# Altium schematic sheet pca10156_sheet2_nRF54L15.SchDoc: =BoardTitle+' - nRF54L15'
size A3; Organization: Nordic Semiconductor; DocumentNumber: 2; SheetNumber: 2; SheetTotal: 7; CompanyName: Nordic Semiconductor; DocumentSize: A4
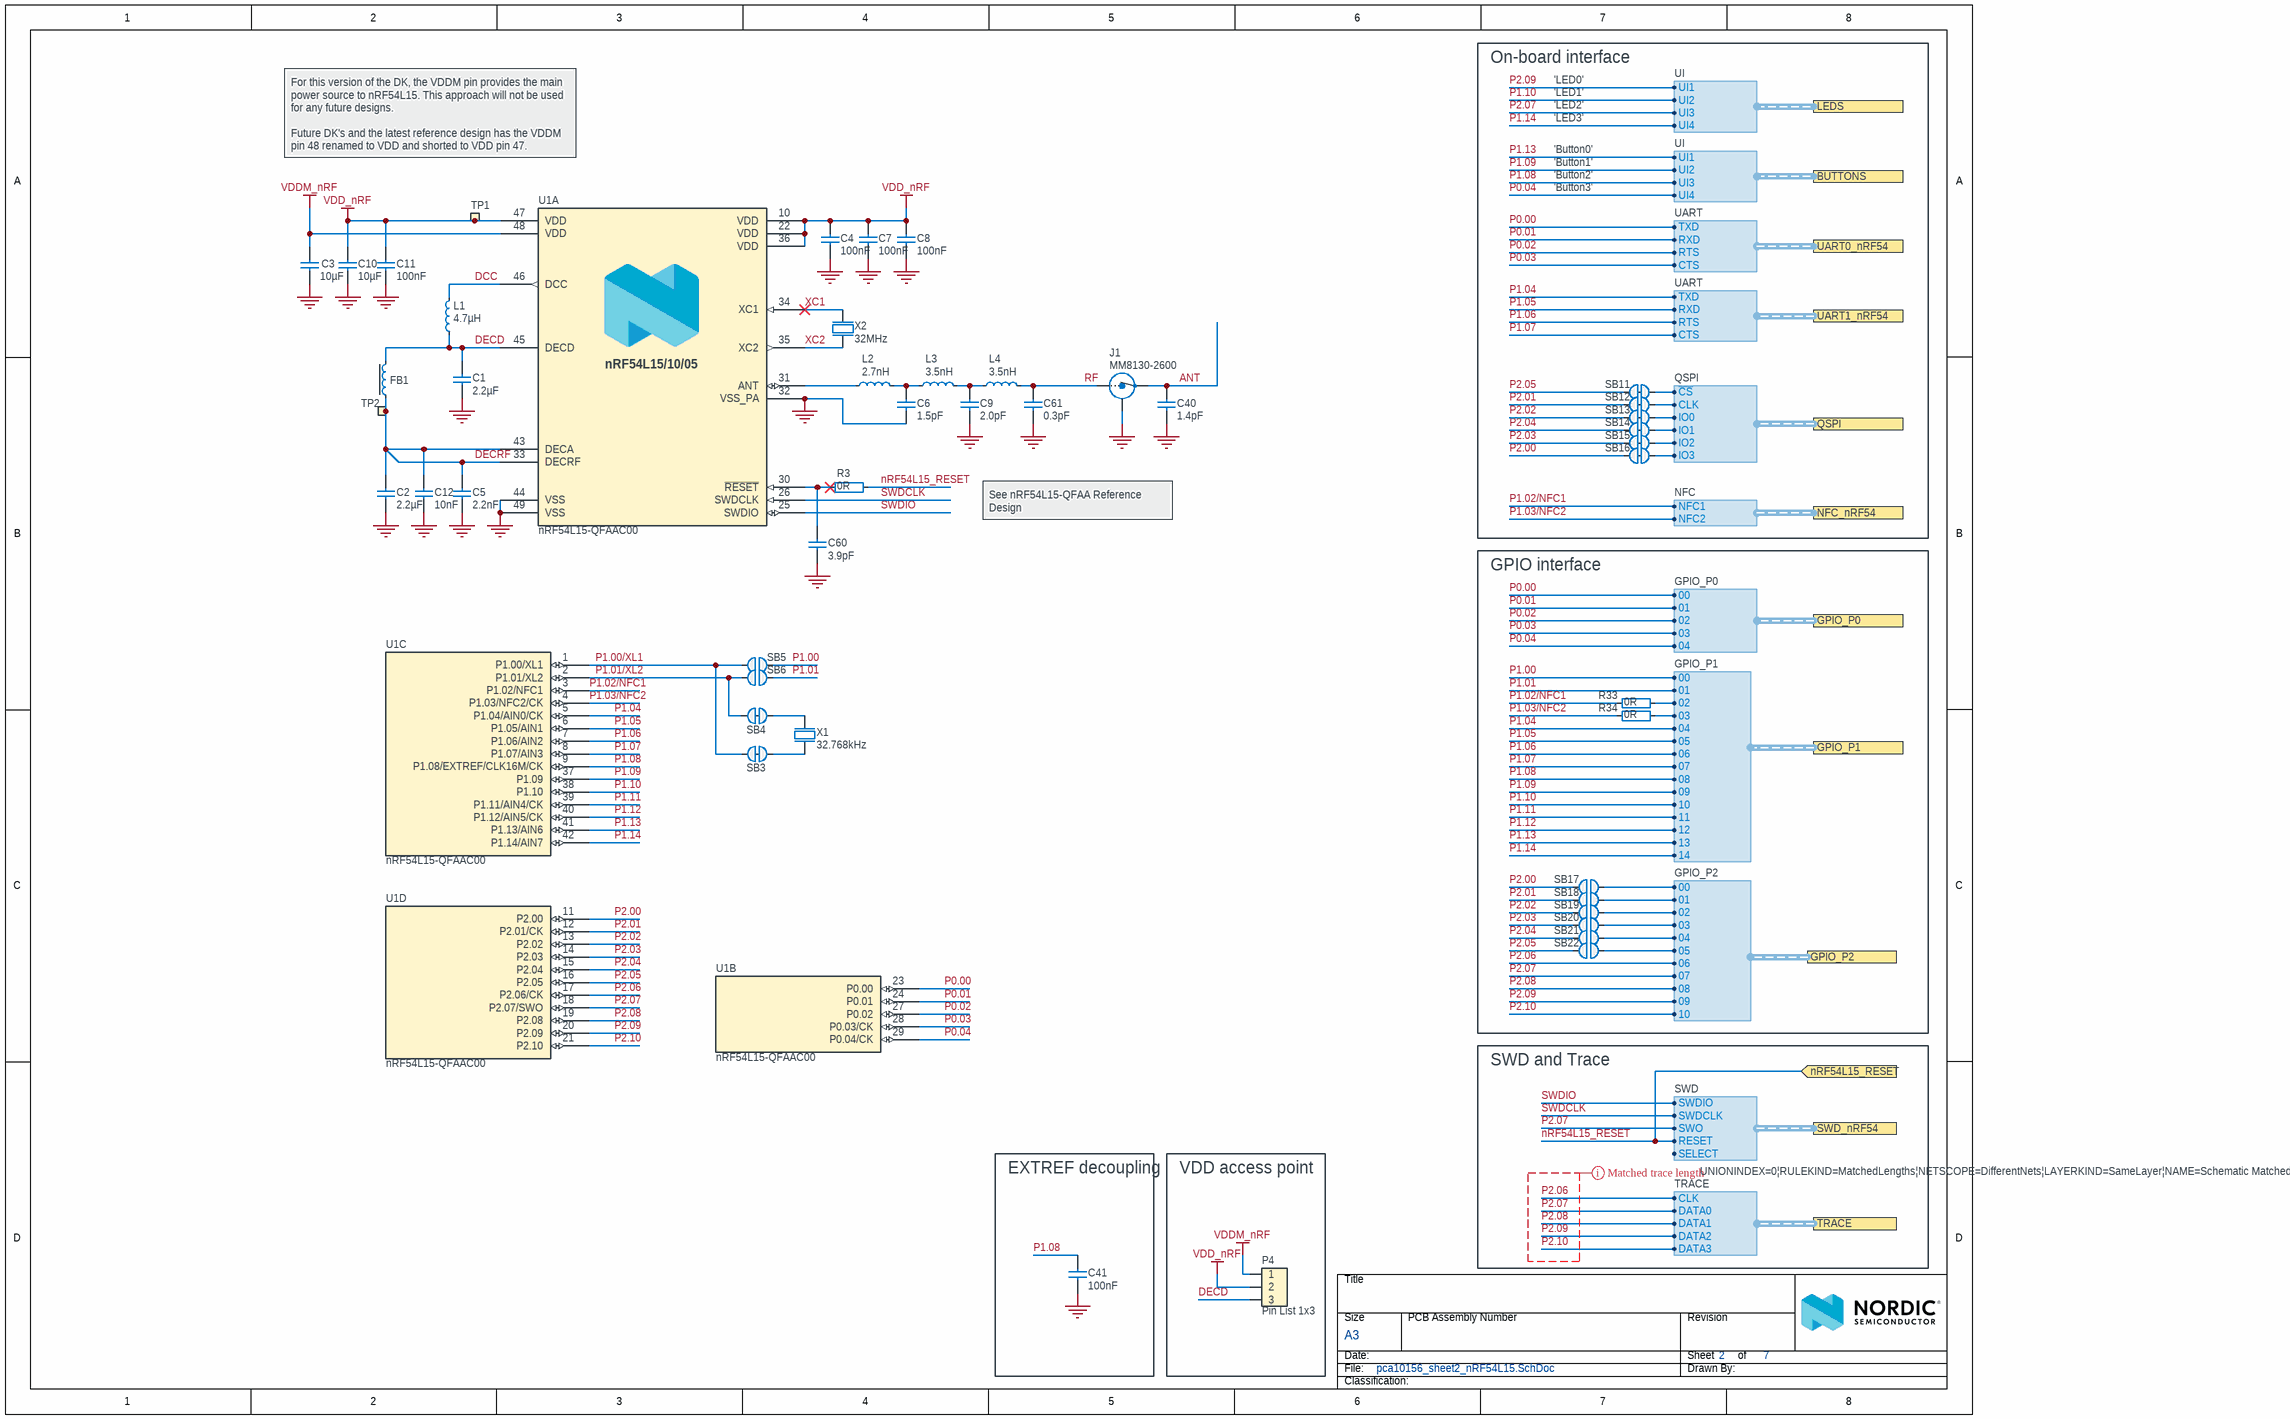
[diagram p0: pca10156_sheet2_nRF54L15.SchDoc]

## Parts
C1  2.2µF  [CAPC0603X03L_C]
C2  2.2µF  [CAPC0603X03L_C]
C3  10µF  [CAPC1005X04L]
C4  100nF  [CAPC0603X03L_C]
C5  2.2nF  [CAPC0603X03L_C]
C6  1.5pF  [CAPC0603X03L_C]
C7  100nF  [CAPC0603X03L_C]
C8  100nF  [CAPC0603X03L_C]
C9  2.0pF  [CAPC0603X03L_C]
C10  10µF  [CAPC1005X04L]
C11  100nF  [CAPC0603X03L_C]
C12  10nF  [CAPC0603X03L_C]
C40  1.4pF  [CAPC0603X03L_C]
C41  100nF  [CAPC1005X04L]
C60  3.9pF  [CAPC0603X03L_C]
C61  0.3pF  [CAPC0603X03L_C]
FB1  120R/0.2A  [INDC0603X03L_C]  (value not drawn)
J1  MM8130-2600  [COAXIAL-SWF]
L1  4.7µH  [INDC1608X06L]
L2  2.7nH  [INDC0603X03L_C]
L3  3.5nH  [INDC0603X03L_C]
L4  3.5nH  [INDC0603X03L_C]
P4  Pin List 1x3  [LIST_1x3]
R3  0R  [RESC0603X03L_C]
R33  0R  [RESC1005X04L]
R34  0R  [RESC1005X04L]
SB3  Solderbridge  [Solderbridge_SHORTED_0.4]  (value not drawn)  (net tie, no BOM)
SB4  Solderbridge  [Solderbridge_SHORTED_0.4]  (value not drawn)  (net tie, no BOM)
SB5  Solderbridge  [Solderbridge_0.4]  (value not drawn)  (no BOM)
SB6  Solderbridge  [Solderbridge_0.4]  (value not drawn)  (no BOM)
SB11  Solderbridge  [Solderbridge_SHORTED_0.4]  (value not drawn)  (net tie, no BOM)
SB12  Solderbridge  [Solderbridge_SHORTED_0.4]  (value not drawn)  (net tie, no BOM)
SB13  Solderbridge  [Solderbridge_SHORTED_0.4]  (value not drawn)  (net tie, no BOM)
SB14  Solderbridge  [Solderbridge_SHORTED_0.4]  (value not drawn)  (net tie, no BOM)
SB15  Solderbridge  [Solderbridge_SHORTED_0.4]  (value not drawn)  (net tie, no BOM)
SB16  Solderbridge  [Solderbridge_SHORTED_0.4]  (value not drawn)  (net tie, no BOM)
SB17  Solderbridge  [Solderbridge_0.4]  (value not drawn)  (no BOM)
SB18  Solderbridge  [Solderbridge_0.4]  (value not drawn)  (no BOM)
SB19  Solderbridge  [Solderbridge_0.4]  (value not drawn)  (no BOM)
SB20  Solderbridge  [Solderbridge_0.4]  (value not drawn)  (no BOM)
SB21  Solderbridge  [Solderbridge_0.4]  (value not drawn)  (no BOM)
SB22  Solderbridge  [Solderbridge_0.4]  (value not drawn)  (no BOM)
TP1  Ø1.5mm,SMD  [TP_SMD_D1.5mm]  (value not drawn)  (no BOM)
TP2  Ø1.5mm,SMD  [TP_SMD_D1.5mm]  (value not drawn)  (no BOM)
U1  nRF54L15-QFAAC00  [QFN40P600X600X90-48N]  (parts A,B,C,D of 4)
X1  32.768kHz  [XTAL_2012]
X2  32MHz  [BT-XTAL_2016]

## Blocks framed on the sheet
On-board interface: SB11-SB16
GPIO interface: R33 R34 SB17-SB22
EXTREF decoupling: C41
VDD access point: P4

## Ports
BUTTONS (harness UI), GPIO_P0 (harness GPIO_P0), GPIO_P1 (harness GPIO_P1), GPIO_P2 (harness GPIO_P2), LEDS (harness UI), NFC_nRF54 (harness NFC), nRF54L15_RESET (in), QSPI (harness QSPI), SWD_nRF54 (harness SWD), TRACE (harness TRACE), UART0_nRF54 (harness UART), UART1_nRF54 (harness UART)

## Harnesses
SWD: SWDIO, SWDCLK, SWO, RESET, SELECT
NFC: NFC2, NFC1
UART: RTS, CTS, RXD, TXD
GPIO_P1: 00, 01, 02, 03, 04, 05, 06, 07, 08, 09, 10, 11, 12, 13, 14
GPIO_P0: 02, 03, 04, 00, 01
GPIO_P2: 00, 01, 02, 03, 04, 05, 06, 07, 08, 09, 10
QSPI: ~{CS}, IO0, CLK, IO1, IO2, IO3
TRACE: CLK, DATA0, DATA1, DATA3, DATA2
UI: UI2, UI1, UI3, UI4

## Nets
GND: C1.1 C2.1 C3.1 C4.2 C5.1 C6.1 C7.2 C8.2 C9.1 C10.1 C11.2 C12.2 C40.1 C41.1 C60.2 C61.1 J1.2(Shield) U1.32(VSS_PA) U1.44(VSS) U1.49(VSS) X2.2(GND) X2.4(GND)
VDD_nRF: C4.1 C7.1 C8.1 C10.2 C11.1 P4.2 TP1.1 U1.10(VDD) U1.22(VDD) U1.36(VDD) U1.47(VDD)
VDDM_nRF: C3.2 P4.1 U1.48(VDD)
ANT: C40.2 J1.3(OUT)
DCC: L1.2 U1.46(DCC)
DECD: C1.2 FB1.1 L1.1 P4.3 U1.45(DECD)
DECRF: C2.2 C5.2 C12.1 FB1.2 TP2.1 U1.33(DECRF) U1.43(DECA)
nRF54L15_RESET: R3.2 ; port nRF54L15_RESET, port SWD_nRF54.RESET
P0.00: U1.23(P0.00) ; port UART0_nRF54.TXD, port GPIO_P0.00
P0.01: U1.24(P0.01) ; port UART0_nRF54.RXD, port GPIO_P0.01
P0.02: U1.27(P0.02) ; port UART0_nRF54.RTS, port GPIO_P0.02
P0.03: U1.28(P0.03/CK) ; port UART0_nRF54.CTS, port GPIO_P0.03
P0.04: U1.29(P0.04/CK) ; port GPIO_P0.04, port BUTTONS.UI4
P1.00: SB5.2 ; port GPIO_P1.00
P1.00/XL1: SB3.1 SB5.1 U1.1(P1.00/XL1)
P1.01: SB6.2 ; port GPIO_P1.01
P1.01/XL2: SB4.1 SB6.1 U1.2(P1.01/XL2)
P1.02/NFC1: R33.1 U1.3(P1.02/NFC1) ; port NFC_nRF54.NFC1
P1.03/NFC2: R34.1 U1.4(P1.03/NFC2/CK) ; port NFC_nRF54.NFC2
P1.04: U1.5(P1.04/AIN0/CK) ; port GPIO_P1.04, port UART1_nRF54.TXD
P1.05: U1.6(P1.05/AIN1) ; port GPIO_P1.05, port UART1_nRF54.RXD
P1.06: U1.7(P1.06/AIN2) ; port GPIO_P1.06, port UART1_nRF54.RTS
P1.07: U1.8(P1.07/AIN3) ; port GPIO_P1.07, port UART1_nRF54.CTS
P1.08: C41.2 U1.9(P1.08/EXTREF/CLK16M/CK) ; port GPIO_P1.08, port BUTTONS.UI3
P1.09: U1.37(P1.09) ; port GPIO_P1.09, port BUTTONS.UI2
P1.10: U1.38(P1.10) ; port GPIO_P1.10, port LEDS.UI2
P1.11: U1.39(P1.11/AIN4/CK) ; port GPIO_P1.11
P1.12: U1.40(P1.12/AIN5/CK) ; port GPIO_P1.12
P1.13: U1.41(P1.13/AIN6) ; port GPIO_P1.13, port BUTTONS.UI1
P1.14: U1.42(P1.14/AIN7) ; port GPIO_P1.14, port LEDS.UI4
P2.00: SB16.1 SB17.2 U1.11(P2.00)
P2.01: SB12.1 SB18.2 U1.12(P2.01/CK)
P2.02: SB13.1 SB19.2 U1.13(P2.02)
P2.03: SB15.1 SB20.2 U1.14(P2.03)
P2.04: SB14.1 SB21.2 U1.15(P2.04)
P2.05: SB11.1 SB22.2 U1.16(P2.05)
P2.06: U1.17(P2.06/CK) ; port GPIO_P2.06, port TRACE.CLK
P2.07: U1.18(P2.07/SWO) ; port SWD_nRF54.SWO, port GPIO_P2.07, port TRACE.DATA0, port LEDS.UI3
P2.08: U1.19(P2.08) ; port GPIO_P2.08, port TRACE.DATA1
P2.09: U1.20(P2.09) ; port GPIO_P2.09, port TRACE.DATA2, port LEDS.UI1
P2.10: U1.21(P2.10) ; port GPIO_P2.10, port TRACE.DATA3
RF: C61.2 J1.1(IN) L4.2
SWDCLK: U1.26(SWDCLK) ; port SWD_nRF54.SWDCLK
SWDIO: U1.25(SWDIO) ; port SWD_nRF54.SWDIO
XC1: U1.34(XC1) X2.1(inp)
XC2: U1.35(XC2) X2.3(out)
NetC6_2: C6.2 L2.2 L3.1
NetC9_2: C9.2 L3.2 L4.1
NetC60_1: C60.1 R3.1 U1.30(~{RESET})
NetL2_1: L2.1 U1.31(ANT)
NetR33_2: R33.2 ; port GPIO_P1.02
NetR34_2: R34.2 ; port GPIO_P1.03
NetSB3_2: SB3.2 X1.2(out)
NetSB4_2: SB4.2 X1.1(inp)
NetSB11_2: SB11.2 ; port QSPI.~{CS}
NetSB12_2: SB12.2 ; port QSPI.CLK
NetSB13_2: SB13.2 ; port QSPI.IO0
NetSB14_2: SB14.2 ; port QSPI.IO1
NetSB15_2: SB15.2 ; port QSPI.IO2
NetSB16_2: SB16.2 ; port QSPI.IO3
NetSB17_1: SB17.1 ; port GPIO_P2.00
NetSB18_1: SB18.1 ; port GPIO_P2.01
NetSB19_1: SB19.1 ; port GPIO_P2.02
NetSB20_1: SB20.1 ; port GPIO_P2.03
NetSB21_1: SB21.1 ; port GPIO_P2.04
NetSB22_1: SB22.1 ; port GPIO_P2.05

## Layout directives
net class TRACE; rule Matched Net Lengths [Delay Tolerance = 500ps]: P2.06, P2.07, P2.08, P2.09, P2.10

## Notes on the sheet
- 'LED1'
- 'LED0'
- For this version of the DK, the VDDM pin provides the main power source to nRF54L15. This approach will not be used for any future designs.
  Future DK's and the latest reference design has the VDDM pin 48 renamed to VDD and shorted to VDD pin 47.
- 'LED2'
- 'LED3'
- 'Button1'
- 'Button0'
- 'Button2'
- 'Button3'
- See nRF54L15-QFAA Reference Design
- SWD and Trace

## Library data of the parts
C1 C2 = C0201-2µ2-2.5V-X6T-GRM033D80E225ME47D: Capacitor, Ceramic, 2.2µF 2.5V X6T 0201,±20%; Manufacturer: Murata; Manufacturer Part Number: GRM033R61A225KE47; Part number NEMS: 100200527; Component Status: Active; Pad Count: 2; Note: 2.5V, 20%, X6T; Artikkelnr Noca: N.A.
C3 C10 = C0402-10µF-6.3V-X6S: Capacitor, X6S, ±20%, 6.3V; Manufacturer: N.A.; Part number NEMS: 100200478; Component Status: Active; Pad Count: 2
C4 C7 C8 C11 = C0201-100n: Capacitor, X5R, ±10%; Manufacturer: N.A.; Part number IPS: 00000001248, 00000002505; Part number Norautron: 262071862; Part number NEMS: 100200078; Pad Count: 2; Note: 16V; Component Status: Active
C5 = C0201-2n2: Capacitor, X7R, ±10%, 10V; Manufacturer: N.A.; Part number IPS: 00000001778; Part number Norautron: 26470002; Part number NEMS: 100200060; Pad Count: 2; Component Status: Active
C6 = C0201-1.5p-25V-NP0-GJM0335C1E1R5WB01: Capacitor, NP0, ±0.05pF, 25V, High Q; Manufacturer: Murata; Part number NEMS: 100200477; Component Status: Active; Pad Count: 2; Artikkelnr Noca: N.A.
C9 = C0201-2.0p-HQ-Murata: Capacitor, NP0, ±0.05pF, 25V; Manufacturer: Murata; Manufacturer Part Number: GJM0335C1E2R0WB01; Part number IPS: 00000001775; Part number NEMS: 100200419; Component Status: Active; Pad Count: 2; Artikkelnr Noca: N.A.
C12 = C0201-10n: Capacitor, X7R, ±10%; Manufacturer: N.A.; Part number IPS: 00000003480; Part number Norautron: 26621779; Part number NEMS: 100200067; Note: 10V; Pad Count: 2; Component Status: Active
C40 = C0201-1.4p-25V-GJM0335C1E1R4WB01D: Capacitor, C0G, ±0.05pF, 25V; Manufacturer: Murata; Part number NEMS: 100200553; Pad Count: 2; Artikkelnr Noca: N.A.; Component Status: Active
C41 = C0402-100n: Capacitor, X7R, ±10%; Manufacturer: N.A.; Part number IPS: 00000005296; Part number NEMS: 100200184; Component Status: Active; Pad Count: 2; Note: 16V; Artikkelnr Noca: 20039200; Assembly: Not Mounted
C60 = C0201-3.9p-HQ-Murata: Capacitor, NP0, ±0.05pF, 25V; Manufacturer: Murata; Manufacturer Part Number: GJM0333C1E3R9WB01; Part number NEMS: 100200424; Component Status: Active; Pad Count: 2; Artikkelnr Noca: N.A.
C61 = C0201-0.3p-50V-GRM0335C1HR30BA01: Capacitor, C0G, ±0.1pF, 50V; Manufacturer: Murata; Part number NEMS: 100200650; Component Status: Active; Pad Count: 2; Artikkelnr Noca: N.A.
FB1 = FB0201-120R@100M-200mA-BLM03AG121SN1D: Ferrite Bead, 120 Ohm @ 100MHz, 200mA, 500 mOhm Max; Manufacturer: Murata; Part number NEMS: 100300419; Component Status: Active; Pad Count: 2; Artikkelnr Noca: N.A.
J1 = MM8130-2600: Coaxial Connector with Switch; Manufacturer: Murata; Part number IPS: 00000009955; Part number Norautron: 26030338; Part number NEMS: 100500400; Component Status: Active; Pad Count: 3; Note: N.A.; Artikkelnr Noca: 55029011
L1 = L0603-4µ7-MLZ1608M4R7WT000: Inductor, 120mA, ±20%, 0.65R; Manufacturer: TDK Corporation; Part number NEMS: 100300440; Component Status: Active; Pad Count: 2; Note: Power Inductor ±20%; Artikkelnr Noca: N.A.
L2 = L0201-2n7-HQ-Murata: Inductor, 600mA, ±0.1ｎH, 120mOhm; Manufacturer: Murata; Manufacturer Part Number: LQP03HQ2N7B02; Part number IPS: 00000001753; Part number NEMS: 100300214; Component Status: Active; Pad Count: 2; Note: -55°C ~ 125°C; Artikkelnr Noca: N.A.
L3 L4 = L0201-3n5-HQ-Murata: Inductor, 500mA, ±0.1ｎH, 170mOhm; Manufacturer: Murata; Manufacturer Part Number: LQP03HQ3N5B02; Part number NEMS: 100300222; Component Status: Active; Pad Count: 2; Note: -55°C ~ 125°C; Artikkelnr Noca: N.A.
P4 = Pin List 1x3: Pin List 1x3, 2.54mm (100mil); Manufacturer: N.A.; Part number NEMS: 100500304; Component Status: Active; Pad Count: 3; Artikkelnr Noca: 56019041; Assembly: Not Mounted; System: Connector
R3 = R0201-0R: Resistor, ±5%, 0.05W; Manufacturer: N.A.; Part number IPS: 00000003245; Part number NEMS: 100100001; Component Status: Active; Pad Count: 2; Note: Chip Res 5%
R33 R34 = R0402-0R: Resistor, ±5%, 0.063W; Manufacturer: N.A.; Part number IPS: 00000007128; Part number NEMS: 100100109; Component Status: Active; Pad Count: 2; Note: Chip Res 5%; Artikkelnr Noca: 27049000; Assembly: Not Mounted
SB3 SB4 SB11-SB16 = Solderbridge Shorted 0.4mm: Shorted Solderbridge; Manufacturer: N.A.; Part number NEMS: 100500561; Component Status: Active; Pad Count: 2; System: Connector
SB5 SB6 SB17-SB22 = Solderbridge 0.4mm: Manufacturer: N.A.; Part number NEMS: 100500560; Component Status: Active; Pad Count: 2; System: Connector
TP1 TP2 = TP_SMD_Ø1.5MM: 1.5mm circular SMD testpad; Manufacturer: Nordic Semiconductor; Manufacturer Part Number: N.A.; Part number NEMS: 100500477; Pad Count: 1; Component Status: Active
U1 = nRF54L15-QFAAC00: Multi-protocol Bluetooth Low Energy, IEEE 802.15.4 and 2.4GHz proprietary Wireless MCU; Manufacturer: Nordic Semiconductor; Part number NEMS: 102000382; Component Status: Active; Pad Count: 49; Note: N.A.
X1 = XTAL_SMD2012_32.768kHz_9pF_TXC: XTAL SMD 2012, 32.768kHz, 9pF, ±20ppm; Manufacturer: TXC Corporation; Manufacturer Part Number: 9HT11-32.768KDZC-T; Part number NEMS: 101600107; Component Status: Active; Pad Count: 2; Note: XTAL SMD 32.768kHz; Artikkelnr Noca: N.A.
X2 = XTAL_SMD2016_32MHz_8pF_Golledge: XTAL SMD 2016, 32MHz, Cl=8pF, Tol: ±10ppm, Stab: ±15ppm; Manufacturer Part Number: MP06003; Part number IPS: 00000001431; Part number Norautron: N.A.; Part number NEMS: 101600041; Component Status: Active; Pad Count: 4; Note: XTAL SMD 32.000MHz; Artikkelnr Noca: 22010050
